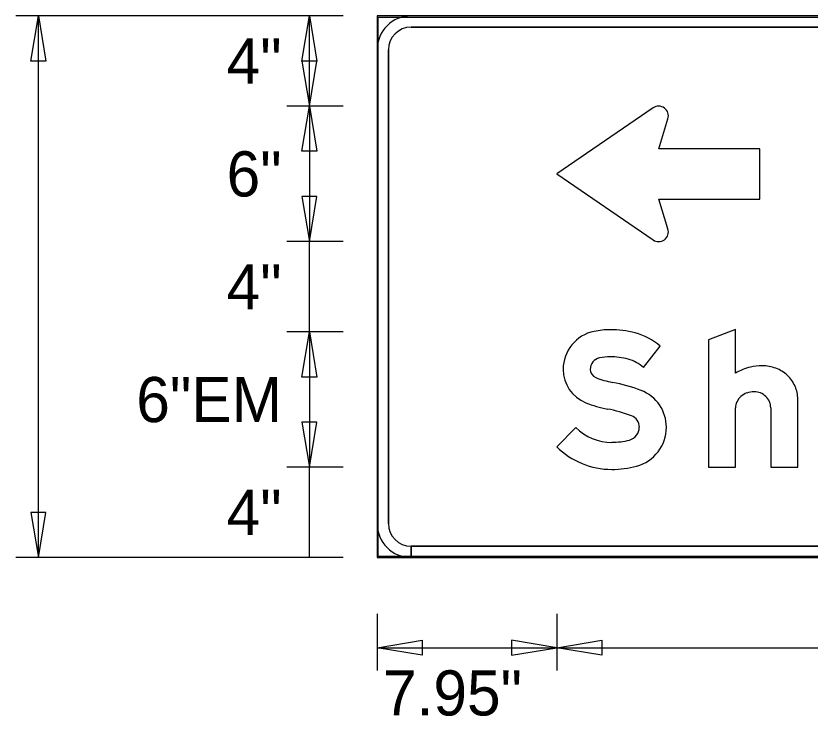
# Model space of a CAD drawing. Extents: x 1374 to 1480, y 568 to 638.
# Drawn here: x 1439.781 to 1442.712, y 598.164 to 600.75 of the extents above; entities that cross this region are included whole.
import ezdxf

# ---------------------------------------------------------------- set-up
doc = ezdxf.new("R2010")
doc.units = 0
for name, color, linetype in [('GSBWFill', 7, 'Continuous'), ('GSColorFill', 7, 'Continuous'), ('GSDims', 7, 'Continuous'), ('GSOutline', 7, 'Continuous')]:
    doc.layers.add(name, color=color, linetype=linetype)

msp = doc.modelspace()

# ---------------------------------------------------------------- linework, layer by layer
at = {"layer": 'GSBWFill'}
for p, q in [((1450.1146, 600.7496), (1441.1146, 600.7496)), ((1441.1146, 600.7496), (1441.1146, 598.7496)), ((1449.9896, 600.7496), (1441.2396, 600.7496)), ((1441.2396, 600.7079), (1449.9896, 600.7079)), ((1441.1146, 600.6246), (1441.1146, 598.8746)), ((1441.1563, 598.8746), (1441.1563, 600.6246)), ((1441.2396, 598.7496), (1441.2396, 598.7912)), ((1449.9896, 598.7912), (1441.24, 598.7912)), ((1441.24, 598.7912), (1441.24, 598.7496)), ((1441.1146, 598.7496), (1450.1146, 598.7496)), ((1441.24, 598.7496), (1449.9896, 598.7496))]:
    msp.add_line(p, q, dxfattribs=at)
for points in [[(1442.133, 600.4097), (1441.7771, 600.166), (1442.133, 599.9224)], [(1442.5271, 600.0733), (1442.5271, 600.2588), (1442.154, 600.2588), (1442.1879, 600.3694)], [(1442.1879, 599.9627), (1442.154, 600.0733), (1442.5271, 600.0733)], [(1442.4371, 599.4297), (1442.4371, 599.5915), (1442.3371, 599.5529), (1442.3371, 599.0827), (1442.4371, 599.0827), (1442.4371, 599.302)], [(1442.0971, 599.4507), (1442.159, 599.5296)], [(1442.5671, 599.302), (1442.5671, 599.0827), (1442.6671, 599.0827), (1442.6671, 599.3349)], [(1441.8475, 599.2297), (1441.7771, 599.1586)]]:
    msp.add_lwpolyline(points, dxfattribs=at)
for centre, radius, start, end in [((1441.2396, 600.6246), 0.125, 90, 180), ((1441.2396, 600.6246), 0.0833, 90, 180), ((1442.1534, 600.38), 0.0361, 342.9427, 124.3997), ((1442.1534, 599.9521), 0.0361, 235.6003, 17.0573), ((1441.9441, 599.4443), 0.1432, 101.6172, 180), ((1441.9746, 599.296), 0.2945, 90, 101.6172), ((1441.9746, 599.2294), 0.3612, 75.2778, 90), ((1442.0081, 599.3569), 0.2293, 48.8597, 75.2778), ((1441.9441, 599.4443), 0.0432, 101.6172, 180), ((1441.9746, 599.296), 0.1945, 90, 101.6172), ((1441.9746, 599.2294), 0.2612, 75.2778, 90), ((1442.0081, 599.3569), 0.1293, 46.4926, 75.2778), ((1442.5356, 599.2577), 0.2, 90, 102.6043), ((1442.5356, 599.3169), 0.1408, 68.8636, 90), ((1441.9336, 599.4443), 0.1327, 180, 248.2079), ((1441.9336, 599.4443), 0.0327, 180, 248.2079), ((1442.5339, 599.2778), 0.1801, 103.4695, 122.4943), ((1442.5389, 599.3257), 0.1314, 46.975, 68.8636), ((1442.0426, 599.7168), 0.3262, 248.2079, 259.4488), ((1441.8714, 598.7977), 0.6087, 69.1129, 79.4488), ((1442.5442, 599.3313), 0.1237, 23.9317, 46.975), ((1442.0365, 599.2303), 0.1457, 0, 69.1129), ((1442.5523, 599.3349), 0.1148, 0, 23.9317), ((1442.4972, 599.2982), 0.0609, 131.0076, 154.5283), ((1442.5024, 599.2923), 0.0688, 109.8074, 131.0076), ((1442.5057, 599.2829), 0.0787, 90, 109.8074), ((1442.5057, 599.2985), 0.0632, 68.0808, 90), ((1442.5064, 599.3002), 0.0613, 45.8298, 68.0808), ((1442.5075, 599.3013), 0.0598, 23.0928, 45.8298), ((1442.0426, 599.7168), 0.4262, 248.2079, 259.4488), ((1442.4892, 599.302), 0.0521, 154.5283, 180), ((1442.5091, 599.302), 0.058, 0, 23.0928), ((1441.8714, 598.7977), 0.5087, 69.1129, 79.4488), ((1442.0365, 599.2303), 0.0457, 360, 69.1129), ((1441.9807, 599.364), 0.1892, 225.2528, 270), ((1442.0336, 599.2303), 0.0485, 284.8926, 360), ((1442.0336, 599.2303), 0.1485, 284.8926, 360), ((1441.9807, 599.4292), 0.2543, 270, 284.8926), ((1441.9807, 599.364), 0.2892, 225.2528, 270), ((1441.9807, 599.4292), 0.3543, 270, 284.8926), ((1441.2396, 598.8746), 0.125, 180, 270), ((1441.2396, 598.8746), 0.0833, 180, 270)]:
    msp.add_arc(centre, radius, start, end, dxfattribs=at)
at = {"layer": 'GSColorFill'}
for p, q in [((1450.1146, 600.7496), (1441.1146, 600.7496)), ((1441.1146, 600.7496), (1441.1146, 598.7496)), ((1450.1146, 600.7496), (1441.1146, 600.7496)), ((1441.1146, 600.7496), (1441.1146, 598.7538)), ((1441.1188, 598.7538), (1441.1188, 600.7454)), ((1441.1188, 600.7454), (1450.1105, 600.7454)), ((1449.9896, 600.7496), (1441.2396, 600.7496)), ((1441.2396, 600.7079), (1449.9896, 600.7079)), ((1441.1146, 600.6246), (1441.1146, 598.8746)), ((1441.1563, 598.8746), (1441.1563, 600.6246)), ((1441.2396, 598.7496), (1441.2396, 598.7912)), ((1449.9896, 598.7912), (1441.24, 598.7912)), ((1441.24, 598.7912), (1441.24, 598.7496)), ((1441.1146, 598.7538), (1441.1188, 598.7538)), ((1450.1105, 598.7537), (1441.1146, 598.7537)), ((1441.1146, 598.7537), (1441.1146, 598.7496)), ((1441.1146, 598.7496), (1450.1146, 598.7496)), ((1441.1146, 598.7496), (1450.1146, 598.7496)), ((1441.24, 598.7496), (1449.9896, 598.7496))]:
    msp.add_line(p, q, dxfattribs=at)
for points in [[(1442.133, 600.4097), (1441.7771, 600.166), (1442.133, 599.9224)], [(1442.5271, 600.0733), (1442.5271, 600.2588), (1442.154, 600.2588), (1442.1879, 600.3694)], [(1442.1879, 599.9627), (1442.154, 600.0733), (1442.5271, 600.0733)], [(1442.4371, 599.4297), (1442.4371, 599.5915), (1442.3371, 599.5529), (1442.3371, 599.0827), (1442.4371, 599.0827), (1442.4371, 599.302)], [(1442.0971, 599.4507), (1442.159, 599.5296)], [(1442.5671, 599.302), (1442.5671, 599.0827), (1442.6671, 599.0827), (1442.6671, 599.3349)], [(1441.8475, 599.2297), (1441.7771, 599.1586)]]:
    msp.add_lwpolyline(points, dxfattribs=at)
for centre, radius, start, end in [((1441.2396, 600.6246), 0.125, 90, 180), ((1441.2396, 600.6246), 0.0833, 90, 180), ((1442.1534, 600.38), 0.0361, 342.9427, 124.3997), ((1442.1534, 599.9521), 0.0361, 235.6003, 17.0573), ((1441.9441, 599.4443), 0.1432, 101.6172, 180), ((1441.9746, 599.296), 0.2945, 90, 101.6172), ((1441.9746, 599.2294), 0.3612, 75.2778, 90), ((1442.0081, 599.3569), 0.2293, 48.8597, 75.2778), ((1441.9441, 599.4443), 0.0432, 101.6172, 180), ((1441.9746, 599.296), 0.1945, 90, 101.6172), ((1441.9746, 599.2294), 0.2612, 75.2778, 90), ((1442.0081, 599.3569), 0.1293, 46.4926, 75.2778), ((1442.5356, 599.2577), 0.2, 90, 102.6043), ((1442.5356, 599.3169), 0.1408, 68.8636, 90), ((1441.9336, 599.4443), 0.1327, 180, 248.2079), ((1441.9336, 599.4443), 0.0327, 180, 248.2079), ((1442.5339, 599.2778), 0.1801, 103.4695, 122.4943), ((1442.5389, 599.3257), 0.1314, 46.975, 68.8636), ((1442.0426, 599.7168), 0.3262, 248.2079, 259.4488), ((1441.8714, 598.7977), 0.6087, 69.1129, 79.4488), ((1442.5442, 599.3313), 0.1237, 23.9317, 46.975), ((1442.0365, 599.2303), 0.1457, 0, 69.1129), ((1442.5523, 599.3349), 0.1148, 0, 23.9317), ((1442.4972, 599.2982), 0.0609, 131.0076, 154.5283), ((1442.5024, 599.2923), 0.0688, 109.8074, 131.0076), ((1442.5057, 599.2829), 0.0787, 90, 109.8074), ((1442.5057, 599.2985), 0.0632, 68.0808, 90), ((1442.5064, 599.3002), 0.0613, 45.8298, 68.0808), ((1442.5075, 599.3013), 0.0598, 23.0928, 45.8298), ((1442.0426, 599.7168), 0.4262, 248.2079, 259.4488), ((1442.4892, 599.302), 0.0521, 154.5283, 180), ((1442.5091, 599.302), 0.058, 0, 23.0928), ((1441.8714, 598.7977), 0.5087, 69.1129, 79.4488), ((1442.0365, 599.2303), 0.0457, 360, 69.1129), ((1441.9807, 599.364), 0.1892, 225.2528, 270), ((1442.0336, 599.2303), 0.0485, 284.8926, 360), ((1442.0336, 599.2303), 0.1485, 284.8926, 360), ((1441.9807, 599.4292), 0.2543, 270, 284.8926), ((1441.9807, 599.364), 0.2892, 225.2528, 270), ((1441.9807, 599.4292), 0.3543, 270, 284.8926), ((1441.2396, 598.8746), 0.125, 180, 270), ((1441.2396, 598.8746), 0.0833, 180, 270)]:
    msp.add_arc(centre, radius, start, end, dxfattribs=at)
at = {"layer": 'GSDims'}
for p, q in [((1439.9896, 600.7496), (1439.7813, 600.7496)), ((1439.8646, 598.7496), (1439.8646, 600.7496)), ((1440.9896, 600.7496), (1439.9896, 600.7496)), ((1440.9896, 600.7496), (1440.7813, 600.7496)), ((1440.8646, 600.416), (1440.8646, 600.7496)), ((1440.9896, 600.416), (1440.7813, 600.416)), ((1440.9896, 600.416), (1440.7813, 600.416)), ((1440.8646, 600.416), (1440.8646, 599.916)), ((1440.9896, 599.916), (1440.7813, 599.916)), ((1440.9896, 599.916), (1440.7813, 599.916)), ((1440.8646, 599.5827), (1440.8646, 599.916)), ((1440.9896, 599.5827), (1440.7813, 599.5827)), ((1440.9896, 599.5827), (1440.7813, 599.5827)), ((1440.8646, 599.5827), (1440.8646, 599.0827)), ((1440.9896, 599.0827), (1440.7813, 599.0827)), ((1440.9896, 599.0827), (1440.7813, 599.0827)), ((1440.8646, 598.7496), (1440.8646, 599.0827)), ((1439.9896, 598.7496), (1439.7813, 598.7496)), ((1440.9896, 598.7496), (1439.9896, 598.7496)), ((1440.9896, 598.7496), (1440.7813, 598.7496)), ((1441.1146, 598.5412), (1441.1146, 598.3329)), ((1441.1146, 598.5412), (1441.1146, 598.3329)), ((1441.7771, 598.5412), (1441.7771, 598.3329)), ((1441.7771, 598.5412), (1441.7771, 598.3329)), ((1441.1146, 598.4162), (1441.7771, 598.4162)), ((1441.7771, 598.4162), (1449.4521, 598.4162))]:
    msp.add_line(p, q, dxfattribs=at)
for points in [[(1439.8646, 600.7496), (1439.8924, 600.5829), (1439.8368, 600.5829)], [(1440.8646, 600.7496), (1440.8924, 600.5829), (1440.8368, 600.5829)], [(1440.8646, 600.416), (1440.8924, 600.5827), (1440.8368, 600.5827)], [(1440.8646, 600.416), (1440.8924, 600.2494), (1440.8368, 600.2494)], [(1440.8646, 599.916), (1440.8924, 600.0827), (1440.8368, 600.0827)], [(1440.8646, 599.5827), (1440.8924, 599.416), (1440.8368, 599.416)], [(1440.8646, 599.0827), (1440.8924, 599.2494), (1440.8368, 599.2494)], [(1439.8646, 598.7496), (1439.8924, 598.9162), (1439.8368, 598.9162)], [(1441.1146, 598.4162), (1441.2813, 598.444), (1441.2813, 598.3884)], [(1441.7771, 598.4162), (1441.6105, 598.444), (1441.6105, 598.3884)], [(1441.7771, 598.4162), (1441.9438, 598.444), (1441.9438, 598.3884)]]:
    msp.add_lwpolyline(points, close=True, dxfattribs=at)
at = {"layer": 'GSOutline'}
for p, q in [((1450.1146, 600.7496), (1441.1146, 600.7496)), ((1441.1146, 600.7496), (1441.1146, 598.7496)), ((1449.9896, 600.7496), (1441.2396, 600.7496)), ((1449.9896, 600.7079), (1441.2396, 600.7079)), ((1441.1146, 600.6246), (1441.1146, 598.8746)), ((1441.1563, 600.6246), (1441.1563, 598.8746)), ((1441.2396, 598.7912), (1449.9896, 598.7912)), ((1441.1146, 598.7496), (1450.1146, 598.7496)), ((1441.2396, 598.7496), (1449.9896, 598.7496))]:
    msp.add_line(p, q, dxfattribs=at)
for points in [[(1442.133, 600.4097), (1441.7771, 600.166), (1442.133, 599.9224)], [(1442.5271, 600.0733), (1442.5271, 600.2588), (1442.154, 600.2588), (1442.1879, 600.3694)], [(1442.1879, 599.9627), (1442.154, 600.0733), (1442.5271, 600.0733)], [(1442.4371, 599.4297), (1442.4371, 599.5915), (1442.3371, 599.5529), (1442.3371, 599.0827), (1442.4371, 599.0827), (1442.4371, 599.302)], [(1442.0971, 599.4507), (1442.159, 599.5296)], [(1442.5671, 599.302), (1442.5671, 599.0827), (1442.6671, 599.0827), (1442.6671, 599.3349)], [(1441.8475, 599.2297), (1441.7771, 599.1586)]]:
    msp.add_lwpolyline(points, dxfattribs=at)
for centre, radius, start, end in [((1441.2396, 600.6246), 0.125, 90, 180), ((1441.2396, 600.6246), 0.0833, 90, 180), ((1442.1534, 600.38), 0.0361, 342.9427, 124.3997), ((1442.1534, 599.9521), 0.0361, 235.6003, 17.0573), ((1441.9441, 599.4443), 0.1432, 101.6172, 180), ((1441.9746, 599.296), 0.2945, 90, 101.6172), ((1441.9746, 599.2294), 0.3612, 75.2778, 90), ((1442.0081, 599.3569), 0.2293, 48.8597, 75.2778), ((1441.9441, 599.4443), 0.0432, 101.6172, 180), ((1441.9746, 599.296), 0.1945, 90, 101.6172), ((1441.9746, 599.2294), 0.2612, 75.2778, 90), ((1442.0081, 599.3569), 0.1293, 46.4926, 75.2778), ((1442.5356, 599.2577), 0.2, 90, 102.6043), ((1442.5356, 599.3169), 0.1408, 68.8636, 90), ((1441.9336, 599.4443), 0.1327, 180, 248.2079), ((1441.9336, 599.4443), 0.0327, 180, 248.2079), ((1442.5339, 599.2778), 0.1801, 103.4695, 122.4943), ((1442.5389, 599.3257), 0.1314, 46.975, 68.8636), ((1442.0426, 599.7168), 0.3262, 248.2079, 259.4488), ((1441.8714, 598.7977), 0.6087, 69.1129, 79.4488), ((1442.5442, 599.3313), 0.1237, 23.9317, 46.975), ((1442.0365, 599.2303), 0.1457, 0, 69.1129), ((1442.5523, 599.3349), 0.1148, 0, 23.9317), ((1442.4972, 599.2982), 0.0609, 131.0076, 154.5283), ((1442.5024, 599.2923), 0.0688, 109.8074, 131.0076), ((1442.5057, 599.2829), 0.0787, 90, 109.8074), ((1442.5057, 599.2985), 0.0632, 68.0808, 90), ((1442.5064, 599.3002), 0.0613, 45.8298, 68.0808), ((1442.5075, 599.3013), 0.0598, 23.0928, 45.8298), ((1442.0426, 599.7168), 0.4262, 248.2079, 259.4488), ((1442.4892, 599.302), 0.0521, 154.5283, 180), ((1442.5091, 599.302), 0.058, 0, 23.0928), ((1441.8714, 598.7977), 0.5087, 69.1129, 79.4488), ((1442.0365, 599.2303), 0.0457, 360, 69.1129), ((1441.9807, 599.364), 0.1892, 225.2528, 270), ((1442.0336, 599.2303), 0.0485, 284.8926, 360), ((1442.0336, 599.2303), 0.1485, 284.8926, 360), ((1441.9807, 599.4292), 0.2543, 270, 284.8926), ((1441.9807, 599.364), 0.2892, 225.2528, 270), ((1441.9807, 599.4292), 0.3543, 270, 284.8926), ((1441.2396, 598.8746), 0.125, 180, 270), ((1441.2396, 598.8746), 0.0833, 180, 270)]:
    msp.add_arc(centre, radius, start, end, dxfattribs=at)

# ---------------------------------------------------------------- texts
at = {"layer": 'GSDims'}
for s, p in [('4"', (1440.5591, 600.4995)), ('6"', (1440.5591, 600.0827)), ('4"', (1440.5591, 599.666)), ('6"EM', (1440.2257, 599.2494)), ('4"', (1440.5591, 598.8328)), ('7.95"', (1441.1363, 598.1662))]:
    msp.add_text(s, height=0.16667, dxfattribs=at).set_placement(p)

doc.saveas('drawing.dxf')
